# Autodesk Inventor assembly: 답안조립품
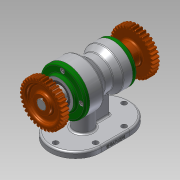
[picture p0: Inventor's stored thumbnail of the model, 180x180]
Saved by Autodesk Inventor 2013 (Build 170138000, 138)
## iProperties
Created: 2020-01
Part Number: 답안조립품
Document SubType Name: Assembly
Designer: Administrator
Author: Administrator
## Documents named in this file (13)
- C:\Users\Administrator\Desktop\700104V1023\답안조립품.iam
- C:\Users\Administrator\Desktop\700104V1023\본체.ipt
- C:\Users\Administrator\Desktop\700104V1023\뒤커버.ipt
- C:\Users\Administrator\Desktop\700104V1023\멈춤나사 M3.ipt
- C:\Users\Administrator\Desktop\700104V1023\베어링 6203.ipt
- C:\Users\Administrator\Desktop\700104V1023\베어링 6205.ipt
- C:\Users\Administrator\Desktop\700104V1023\볼트 M4.ipt
- C:\Users\Administrator\Desktop\700104V1023\스퍼기어.ipt
- C:\Users\Administrator\Desktop\700104V1023\앞커버.ipt
- C:\Users\Administrator\Desktop\700104V1023\오일 실 17 30 8.ipt
- C:\Users\Administrator\Desktop\700104V1023\오일 실 25 38 8.ipt
- C:\Users\Administrator\Desktop\700104V1023\축.ipt
- C:\Users\Administrator\Desktop\700104V1023\키 5 x 5 x 18.ipt
